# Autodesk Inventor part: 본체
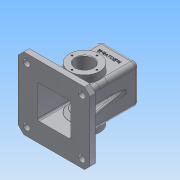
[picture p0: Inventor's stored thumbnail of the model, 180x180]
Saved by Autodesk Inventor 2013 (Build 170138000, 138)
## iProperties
Created: 2016-02
Part Number: 본체
Material: 알루미늄 6061
Document SubType Name: Modeling
Designer: Administrator
Density: 2.71 g/cm^3
Mass: 933.487 g
Surface Area: 1043.49 cm^2
Volume: 344.46 cm^3
Author: Administrator
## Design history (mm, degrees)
sketch "스케치1"
  geometry: L1 (35, -35)-(-35, -35); L2 (-35, -35)-(-35, 35); L3 (-35, 35)-(35, 35); L4 (35, 35)-(35, -35); L5 (35, -35)-(-35, 35); L6 (-35, -35)-(35, 35); 1 further point
  constraints: 12 end point, 2 midpoint, 2 parallel, 1 horizontal, 1 perpendicular
  dimensions: "d0" = 70 distance of L2.end L3.end; "d1" = 70 distance of L1.end L2.end
extrude "돌출1" new body sketch "스케치1" distance "d2" = 120; taper "d3" = 0 deg
feature "쉘1" dims "d29" = 5
sketch "스케치3"
  geometry: C1 r 27.5 at (0, 55); 1 further point
  constraints: 1 centre point, 1 vertical alignment
  dimensions: "d7" = 55 diameter of C1; "d8" = 55 distance of point (0, 0) C1.centre
extrude "돌출2" join sketch "스케치3" stored distance "d9" = 96; taper "d10" = 0 deg
sketch "스케치4"
  geometry: C1 r 20 at (0, 0); 1 further point
  constraints: 1 centre point, 1 coincident
  dimensions: "d11" = 40 diameter of C1
extrude "돌출3" join sketch "스케치4" distance "d12" = 10; taper "d13" = -10 deg
sketch "스케치5"
  geometry: L1 (-35, 35)-(-35, -35) reference; L2 (-35, -35)-(35, -35) reference; L3 (35, -35)-(35, 35) reference; L4 (35, 35)-(-35, 35) reference; L5 (-65, -65)-(65, -65); L6 (65, -65)-(65, 65); L7 (65, 65)-(-65, 65); L8 (-65, 65)-(-65, -65); L9 (-65, -65)-(65, 65); L10 (65, -65)-(-65, 65); A1 r 8 centre (-27, 27) between (-27, 35) and (-35, 27) reference; A2 r 8 centre (-27, -27) between (-35, -27) and (-27, -35) reference; A3 r 8 centre (27, -27) between (27, -35) and (35, -27) reference; A4 r 8 centre (27, 27) between (35, 27) and (27, 35) reference; 1 further point
  constraints: 12 end point, 2 midpoint, 2 parallel, 1 horizontal, 1 perpendicular
  dimensions: "d14" = 130 distance of L7.end L6.end; "d15" = 130 distance of L6.end L5.end
extrude "돌출4" join sketch "스케치5" distance "d16" = 10; taper "d17" = 0 deg
chamfer "모따기1" distance "d18" = 10; stored, may be unused: second distance "d19" = 2, angle "d20" = 45 deg
sketch "스케치6"
  geometry: L1 (35, 120)-(35, 10) reference; L2 (35, 10)-(65, 10) reference; L3 (65, 10)-(65, 0) reference; L4 (65, 0)-(30, 0) reference; L5 (-65, 0)-(-65, 10) reference; L6 (-65, 10)-(-35, 10) reference; L7 (-35, 10)-(-35, 120) reference; L8 (-35, 120)-(-20, 120) reference; L9 (-20, 120)-(-18.237, 130) reference; L10 (-18.237, 130)-(18.237, 130) reference; L11 (18.237, 130)-(20, 120) reference; L12 (20, 120)-(35, 120) reference; L13 (50, 10)-(35, 95.069); L14 (30, 0)-(30, 115) reference; L15 (-30, 115)-(-30, 0) reference; L16 (-30, 0)-(-65, 0) reference; L17 (30, 115)-(-30, 115) reference; C1 r 27.5 at (0, 55) reference; 1 further point
  constraints: 2 end point, 1 midpoint, 1 point on line
  dimensions: "d21" = 15 distance of L2.end L13.start; "d22" = 10 deg angle of L13 L3
feature "리브1" sketch "스케치6" dims "d23" = 1, "d24" = 10, "d25" = 0, "d26" = 0, "d27" = 1, "d28" = 1
extrude "돌출5" cut sketch "스케치3" stored distance "d30" = 60; taper "d31" = 0 deg
hole "구멍1" diameter "d37" = 21; stored, may be unused: countersink angle "d41" = 90 deg, drill point angle "d43" = 118 deg; dims "d35" = 10, "d36" = 10, "d38" = 6, "d39" = 28, "d40" = 4, "d42" = 8
sketch "스케치8"
  geometry: C1 r 27.5 at (27, 55); A1 r 27.5 centre (27, 55) between (0, 60.22) and (0, 49.78) reference; 1 further point
  constraints: 1 centre point, 1 coincident
  dimensions: "d44" = 55 diameter of C1
extrude "돌출7" join sketch "스케치8" distance "d45" = 7; taper "d46" = -45 deg
sketch "스케치7"
  geometry: C1 r 27.5 at (0, 0) reference; C2 r 16 at (0, 0); 1 further point
  constraints: 1 centre point, 1 coincident
  dimensions: "d32" = 32 diameter of C2
extrude "돌출6" cut sketch "스케치7" stored distance "d33" = 60; taper "d34" = 0 deg
sketch "스케치9"
  geometry: C1 r 16 at (0, 0) reference; 2 further points
  constraints: 1 vertical alignment
  dimensions: "d47" = 22.5 distance of C1.centre point (0, 22.5)
hole "구멍2" sketch "스케치9" at (0, 22.5) diameter "d48" = 3.242; stored, may be unused: countersink angle "d52" = 90 deg, drill point angle "d54" = 118 deg; dims "d49" = 8, "d50" = 28, "d51" = 4, "d53" = 10
fillet "모깎기3" dims "d58" = 0.5
chamfer "모따기2" distance "d59" = 1; stored, may be unused: second distance "d60" = 2, angle "d61" = 45 deg
sketch "스케치10"
  geometry: L1 (65, -55)-(65, 55) reference; L2 (55, 65)-(-55, 65) reference; 2 further points
  dimensions: "d62" = 15 distance from line of point (50, 50) L1; "d63" = 15 distance from line of point (50, 50) L2
hole "구멍3" sketch "스케치10" at (50, 50) diameter "d64" = 12; stored, may be unused: countersink angle "d68" = 90 deg, drill point angle "d70" = 118 deg; dims "d65" = 8, "d66" = 28, "d67" = 4, "d69" = 10
fillet "모깎기4" dims "d77" = 3
fillet "모깎기5" dims "d78" = 0.5
fillet "모깎기6" dims "d79" = 8
fillet "모깎기7" dims "d80" = 8
fillet "모깎기8" dims "d81" = 3
fillet "모깎기9" dims "d82" = 3
sketch "스케치11"
  geometry: L1 (27, 65)-(-27, 65) reference; L2 (35, 7.416)-(35, 57) reference; L3 (-18.237, 75)-(18.237, 75) reference; 2 further points
  constraints: 1 other
  dimensions: "d86" = 35 distance from line of L2 point (0, 45); "d87" = 30 distance from line of L3 point (0, 45)
feature "엠보싱1" sketch "스케치11" dims "d88" = 0.5, "d89" = 0
fillet "모깎기12" dims "d90" = 3
fillet "모깎기13" dims "d91" = 3
fillet "모깎기14" dims "d92" = 3
fillet "모깎기15" dims "d93" = 3
fillet "모깎기16" dims "d94" = 3
node "솔리드1"
mirror "대칭1"
mirror "대칭2"
pattern_circular "원형 패턴1" dims angle "d56" = 360 deg
mirror "대칭3"
pattern_linear "직사각형 패턴1" dims "d73" = 100
node "절단 모서리 투영1"
